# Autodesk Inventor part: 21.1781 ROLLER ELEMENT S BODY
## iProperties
Created: 2007-05
Part Number: 21.1781 ROLLER ELEMENT S BODY
Material: PVC-U
Document SubType Name: Modeling
Designer: Andy Moles
Mass: 13.6675 g
Surface Area: 46.9354 cm^2
Volume: 9.7625 cm^3
Density: 1.4 g/cm^3
Author: Andy Moles
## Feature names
1. Revolution1
